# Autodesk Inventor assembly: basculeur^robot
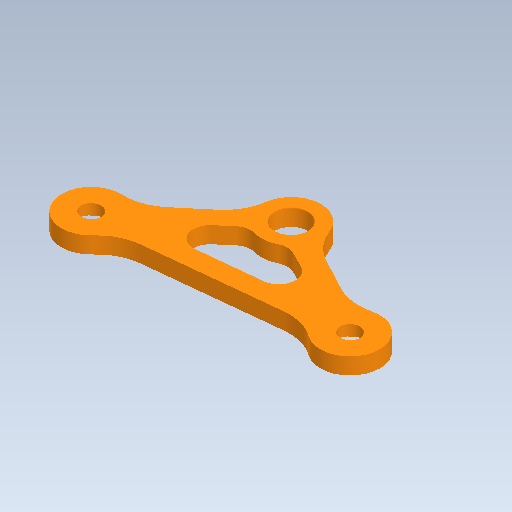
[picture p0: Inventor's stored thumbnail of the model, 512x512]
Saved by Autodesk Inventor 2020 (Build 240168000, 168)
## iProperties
Created: 2018-10
Part Number: basculeur^robot
Document SubType Name: Assembly
Designer: bruno
Sending System: SolidWorks 2016
Last Author: Prof
Last Saved: 2018-10-03
Author: bruno
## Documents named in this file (2)
- C:\Users\bruno\Documents\Systèmes\Mallette Bras robotisé (273265)\Dossier ressources\Maquette Dobot SW2016\basculeur^robot.iam
- C:\Users\bruno\Documents\Systèmes\Mallette Bras robotisé (273265)\Dossier ressources\Maquette Dobot SW2016\____30_A.ipt
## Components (1 placed, 1 different names)
1. ____30_A:1
